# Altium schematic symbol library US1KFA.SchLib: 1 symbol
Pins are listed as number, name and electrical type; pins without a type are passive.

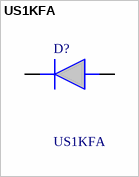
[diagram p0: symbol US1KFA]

## US1KFA
designator D?
Diode Switching 800V 1A 2-Pin SOD-123FA T/R; Manufacturer_Name: onsemi; Geometry.Height: 1.43mm
footprint SODFL3618X143N
pins: 1 K, 2 A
